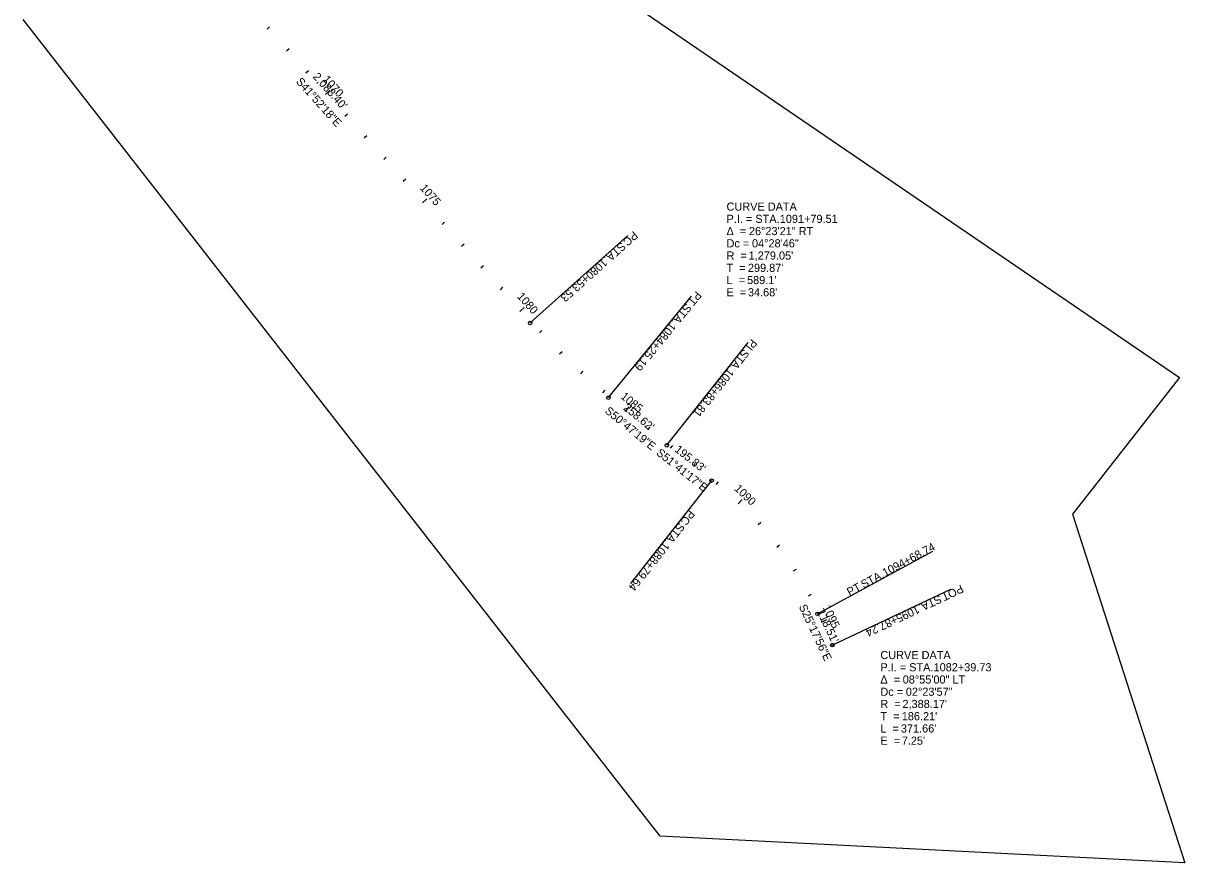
# Model space of a CAD drawing. Extents: x 1845666 to 1851778, y 577180 to 584275.
# Drawn here: x 1847791 to 1851778, y 577180 to 580062 of the extents above; entities that cross this region are included whole.
import ezdxf

# ---------------------------------------------------------------- set-up
doc = ezdxf.new("R2010")
doc.units = 0
for name, color, linetype in [('GE_P_Alignment_500_Bearings', 7, 'Continuous'), ('GE_P_Alignment_500_Cardinal_Points', 7, 'Continuous'), ('GE_P_Alignment_500_Curve_Data', 7, 'Continuous'), ('GE_P_Alignment_500_Distances', 7, 'Continuous'), ('GE_P_Alignment_500_Stations', 7, 'Continuous'), ('SC_Scratch1', 7, 'Continuous')]:
    doc.layers.add(name, color=color, linetype=linetype)

msp = doc.modelspace()

# ---------------------------------------------------------------- linework, layer by layer
at = {"layer": 'GE_P_Alignment_500_Cardinal_Points'}
for p, q in [((1849531.4, 579033.1), (1849866.5, 579333.5)), ((1849800, 578776.8), (1850084.4, 579125.4)), ((1850000.3, 578613.3), (1850279.3, 578966.3)), ((1850154, 578491.9), (1849875, 578138.8)), ((1850517.4, 578034.8), (1850912.9, 578249.5)), ((1850568.1, 577927.7), (1850974.9, 578120))]:
    msp.add_line(p, q, dxfattribs=at)
for centre in [(1849531.4, 579033.1), (1849800, 578776.8), (1850000.3, 578613.3), (1850154, 578491.9), (1850517.4, 578034.8), (1850568.1, 577927.7)]:
    msp.add_circle(centre, 6, dxfattribs=at)
at = {"layer": 'GE_P_Alignment_500_Stations'}
for p, q in [((1848628, 580041), (1848636.9, 580049)), ((1848694.7, 579966.6), (1848703.6, 579974.6)), ((1848761.5, 579892.1), (1848770.4, 579900.1)), ((1848828.2, 579817.6), (1848843.1, 579831)), ((1848894.9, 579743.2), (1848903.9, 579751.2)), ((1848961.7, 579668.7), (1848970.6, 579676.7)), ((1849028.4, 579594.2), (1849037.4, 579602.2)), ((1849095.2, 579519.8), (1849104.1, 579527.8)), ((1849161.9, 579445.3), (1849176.8, 579458.7)), ((1849228.7, 579370.8), (1849237.6, 579378.8)), ((1849295.4, 579296.4), (1849304.4, 579304.4)), ((1849362.2, 579221.9), (1849371.1, 579229.9)), ((1849428.9, 579147.4), (1849437.9, 579155.5)), ((1849495.7, 579073), (1849510.6, 579086.3)), ((1849562.7, 578998.8), (1849571.5, 579007)), ((1849632.4, 578927.1), (1849640.9, 578935.7)), ((1849705.1, 578858.4), (1849713.1, 578867.3)), ((1849780.5, 578792.8), (1849788.2, 578802)), ((1849857.9, 578729.5), (1849870.6, 578745)), ((1849935.4, 578666.2), (1849943, 578675.5)), ((1850013, 578603.2), (1850020.5, 578612.6)), ((1850091.5, 578541.2), (1850099, 578550.6)), ((1850169.9, 578479.1), (1850177.5, 578488.4)), ((1850244.8, 578412.9), (1850258.6, 578427.4)), ((1850314.3, 578341.1), (1850323.3, 578349.1)), ((1850378, 578264), (1850387.5, 578271.3)), ((1850435.5, 578182.2), (1850445.6, 578188.7)), ((1850486.4, 578096.2), (1850497, 578101.9)), ((1850530.8, 578006.6), (1850548.9, 578015.1))]:
    msp.add_line(p, q, dxfattribs=at)
at = {"layer": 'SC_Scratch1'}
msp.add_line((1849977.1, 577272.2), (1847791.3, 580074.7), dxfattribs=at)
for points in [[(1849055, 580692.4), (1851759.8, 578846), (1851393, 578376.5)], [(1851393, 578376.5), (1851777.9, 577180.5), (1849977.1, 577272.2)]]:
    msp.add_lwpolyline(points, dxfattribs=at)

# ---------------------------------------------------------------- texts
at = {"layer": 'GE_P_Alignment_500_Bearings'}
for s, rotation, p in [('S41°52\'18"E', 311.8718, (1848725.7, 579860.1)), ('S50°47\'19"E', 320.7885, (1849785.1, 578727)), ('S51°41\'17"E', 321.6881, (1849961.6, 578582.7)), ('S25°17\'56"E', 295.299, (1850452.6, 578059.7))]:
    msp.add_text(s, height=28, rotation=rotation, dxfattribs=at).set_placement(p)
at = {"layer": 'GE_P_Alignment_500_Cardinal_Points'}
for s, rotation, p in [('PC', 221.8718, (1849885.6, 579350.1)), (' STA. ', 221.8718, (1849851.5, 579319.5)), ('1080+53.53', 221.8718, (1849781.1, 579256.4)), ('PT', 230.7885, (1850100.5, 579144.5)), (' STA. ', 230.7885, (1850072.6, 579110.3)), ('1084+25.19', 230.7885, (1850012.9, 579037.1)), ('PI', 231.6881, (1850290.9, 578980.3)), (' STA. ', 231.6881, (1850269.9, 578953.7)), ('1086+83.81', 231.6881, (1850211.3, 578879.6)), ('PC', 231.6881, (1850077, 578393.8)), (' STA. ', 231.6881, (1850048.6, 578357.8)), ('1088+79.64', 231.6881, (1849990, 578283.6)), ('1094+68.74', 28.4893, (1850749.4, 578161.2)), ('PT', 28.4893, (1850627.6, 578095.1)), (' STA. ', 28.4893, (1850666.4, 578116.1)), ('POT', 205.299, (1851009.8, 578136)), ('1095+87.24', 205.299, (1850859.3, 578064.9)), (' STA. ', 205.299, (1850944.7, 578105.3))]:
    msp.add_text(s, height=28, rotation=rotation, dxfattribs=at).set_placement(p)
at = {"layer": 'GE_P_Alignment_500_Curve_Data'}
for s, p in [('CURVE DATA', (1850205.2, 579418.5)), ('P.I. = STA. ', (1850205.2, 579376.5)), ('1091+79.51', (1850387.9, 579376.5)), ('Δ  = ', (1850205.2, 579334.5)), ('26°23\'21" RT', (1850282, 579334.5)), ('Dc = ', (1850205.2, 579292.5)), ('04°28\'46"', (1850292.6, 579292.5)), ('R  = ', (1850205.2, 579250.5)), ("1,279.05'", (1850281, 579250.5)), ('T  = ', (1850205.2, 579208.5)), ("299.87'", (1850278.6, 579208.5)), ('L  = ', (1850205.2, 579166.5)), ("589.1'", (1850275.6, 579166.5)), ('E  = ', (1850205.2, 579124.5)), ("34.68'", (1850278.6, 579124.5)), ('CURVE DATA', (1850733.2, 577879.5)), ('P.I. = STA. ', (1850733.2, 577837.5)), ('1082+39.73', (1850915.8, 577837.5)), ('Δ  = ', (1850733.2, 577795.5)), ('08°55\'00" LT', (1850809.9, 577795.5)), ('Dc = ', (1850733.2, 577753.5)), ('02°23\'57"', (1850820.6, 577753.5)), ('R  = ', (1850733.2, 577711.5)), ("2,388.17'", (1850809, 577711.5)), ('T  = ', (1850733.2, 577669.5)), ("186.21'", (1850806.6, 577669.5)), ('L  = ', (1850733.2, 577627.5)), ("371.66'", (1850803.6, 577627.5)), ('E  = ', (1850733.2, 577585.5)), ("7.25'", (1850806.6, 577585.5))]:
    msp.add_text(s, height=28, dxfattribs=at).set_placement(p)
at = {"layer": 'GE_P_Alignment_500_Distances'}
for s, rotation, p in [("2,088.40'", 311.8718, (1848783.4, 579877)), ("258.62'", 320.7885, (1849848.7, 578737.6)), ("195.83'", 321.6881, (1850025, 578594.3)), ("118.51'", 295.299, (1850514.6, 578041.8))]:
    msp.add_text(s, height=28, rotation=rotation, dxfattribs=at).set_placement(p)
at = {"layer": 'GE_P_Alignment_500_Stations'}
for s, rotation, p in [('1070', 311.8718, (1848817, 579867.6)), ('1075', 311.8718, (1849151, 579494.9)), ('1080', 311.8718, (1849484.5, 579122.9)), ('1085', 320.7885, (1849839.5, 578776.8)), ('1090', 316.2964, (1850229.8, 578461.8)), ('1095', 295.299, (1850534.5, 578057.2))]:
    msp.add_text(s, height=28, rotation=rotation, dxfattribs=at).set_placement(p)

doc.saveas('drawing.dxf')
